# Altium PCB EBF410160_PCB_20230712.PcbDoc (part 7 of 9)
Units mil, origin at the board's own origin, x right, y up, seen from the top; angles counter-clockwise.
Board outline 5393.69 x 3858.26 mil, 6 copper layers (TOP, GND02, ART03, POW04, GND05, BOTTOM), stack 47.2 mil thick; 572 components, 434 nets, 2057 pads, 1177 vias.
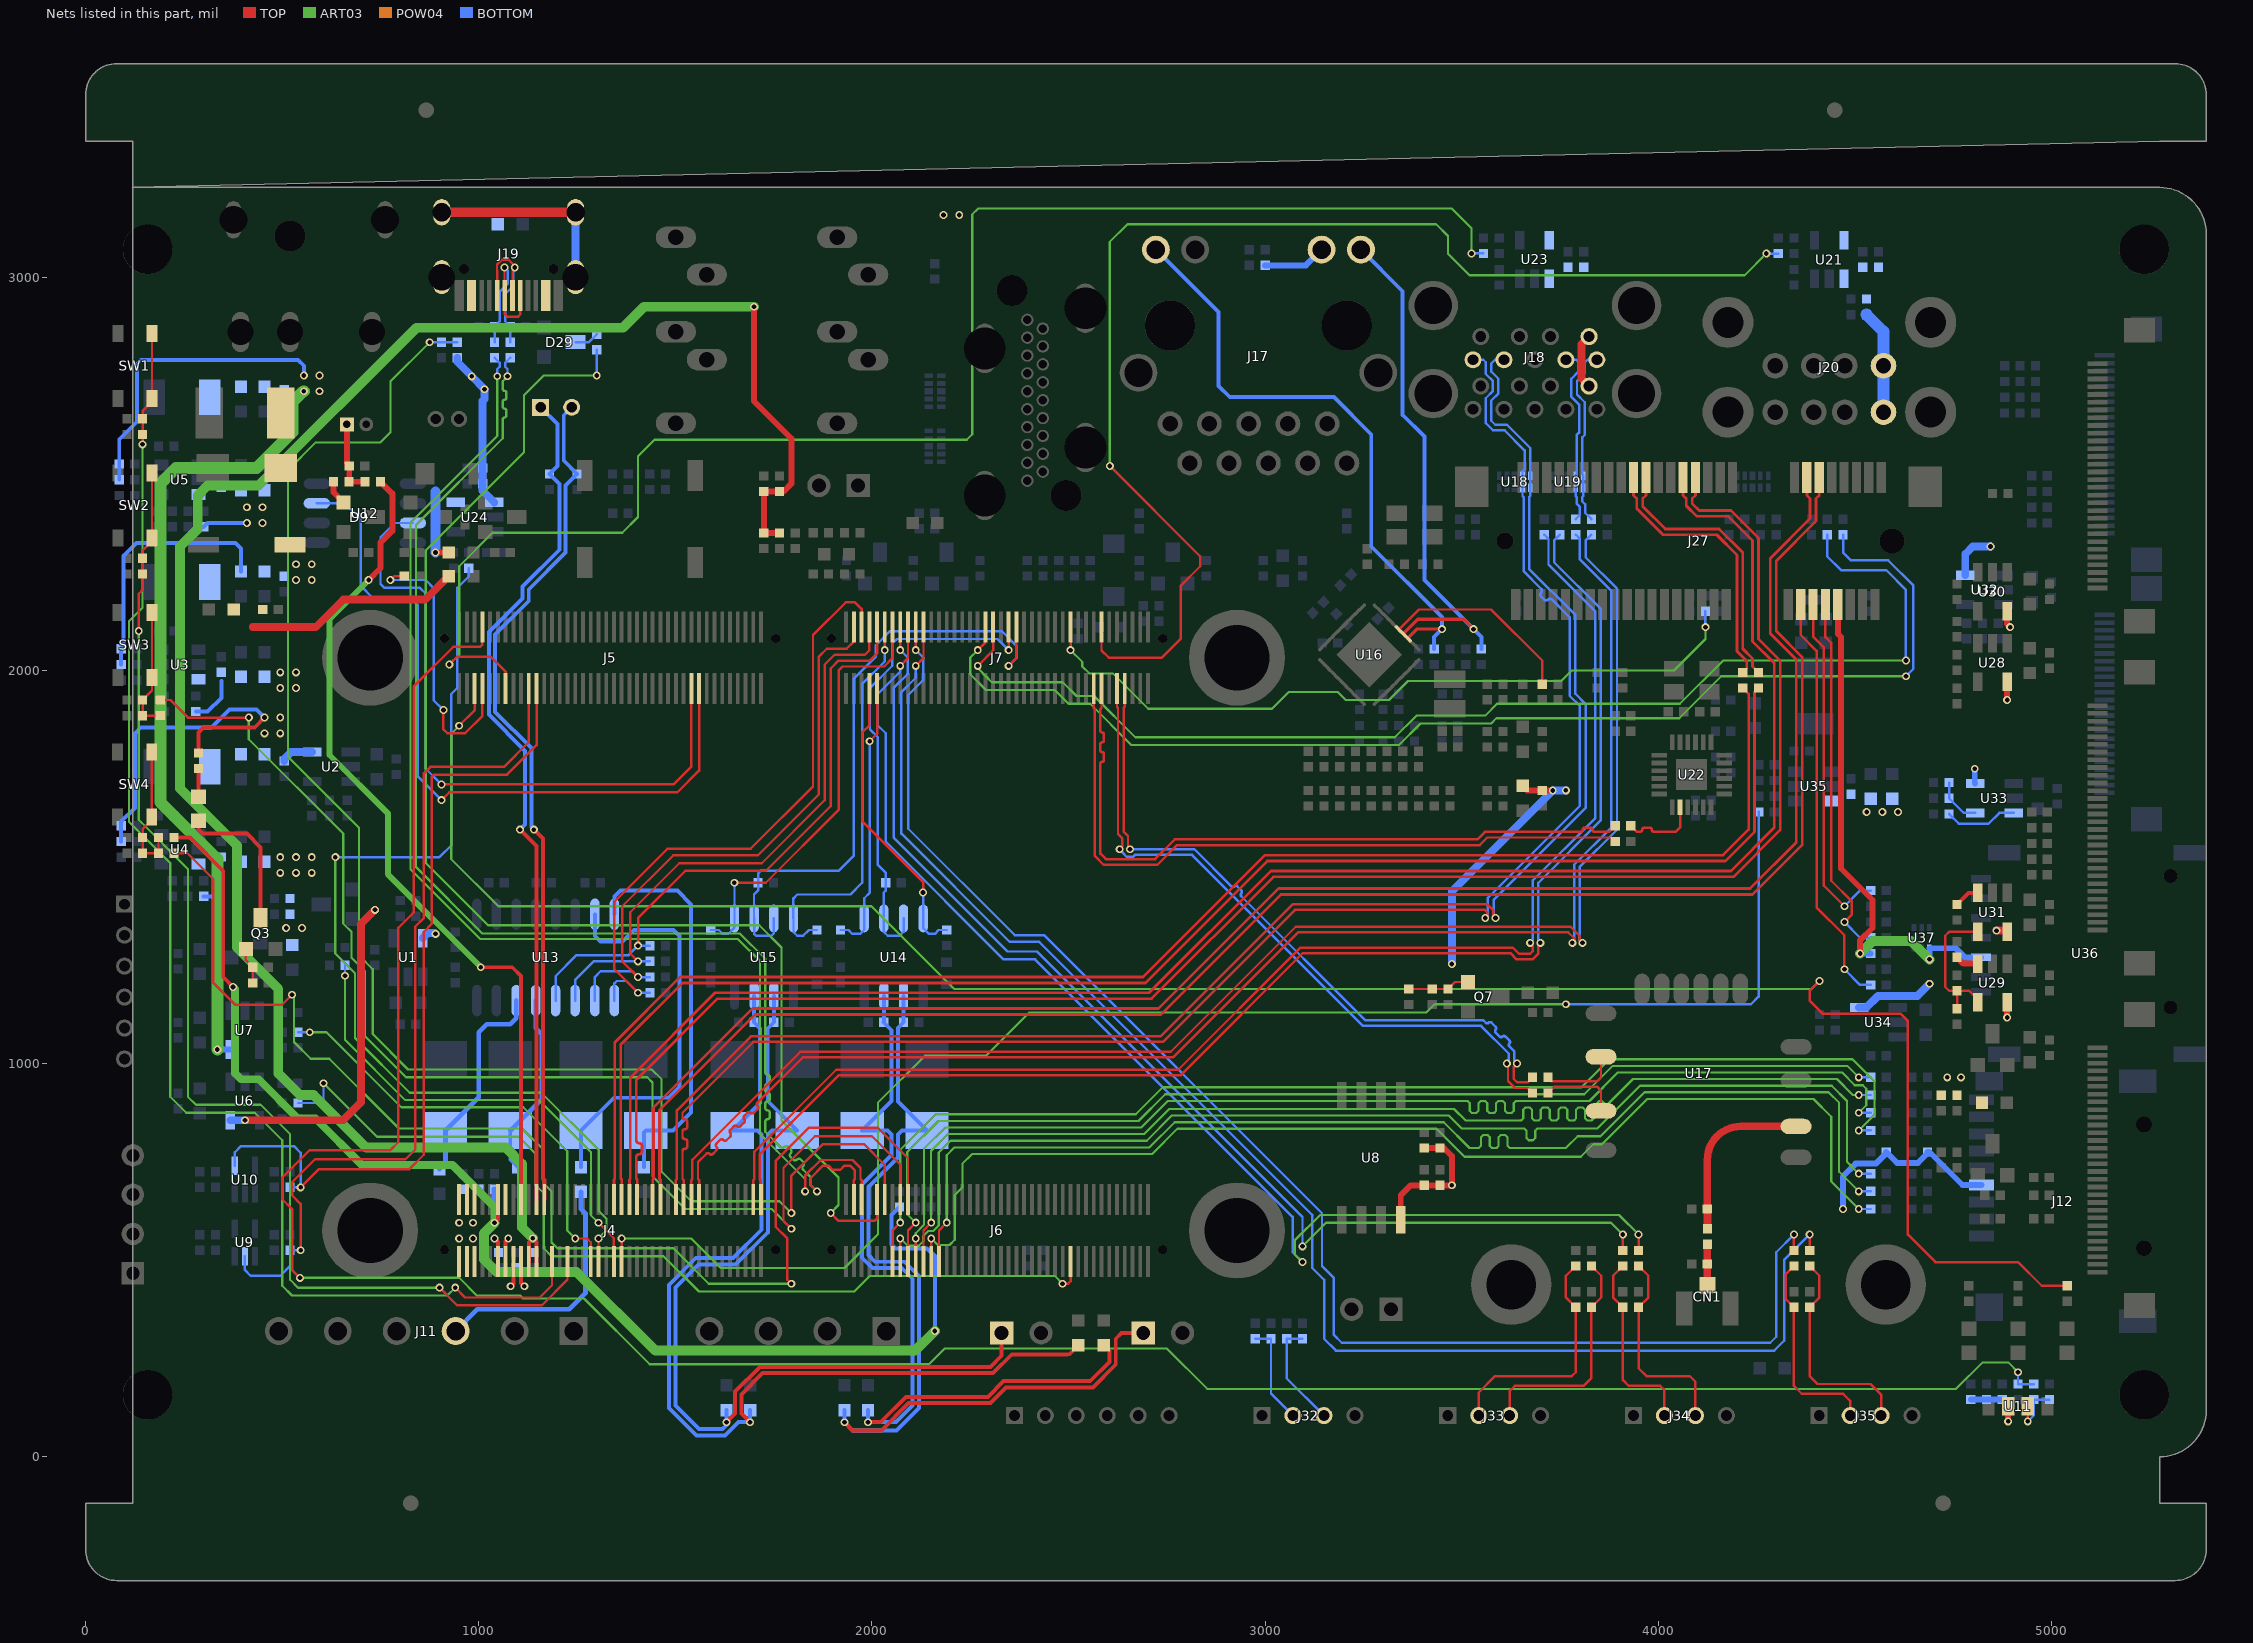
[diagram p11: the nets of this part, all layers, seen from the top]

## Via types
v1: diameter 20, hole 12, TOP to BOTTOM, 1177 vias

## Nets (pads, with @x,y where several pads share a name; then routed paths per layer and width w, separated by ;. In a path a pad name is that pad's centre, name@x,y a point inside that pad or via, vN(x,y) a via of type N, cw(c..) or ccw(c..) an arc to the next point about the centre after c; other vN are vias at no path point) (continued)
N17770942: R142.1 U22.14 | length 201
  TOP w6.23: R142.1@3929.68,1605 3945.45,1589.23 3953.55,1589.23 ccw(c3953.55,1594.62) 3958.94,1594.62 cw(c3964.32,1594.62) 3964.32,1600 3978.47,1600 cw(c3978.47,1594.62) 3983.86,1594.62 ccw(c3989.24,1594.62) 3989.24,1589.23 4044.11,1589.23 4055.47,1600.59 U22.14@4055.47,1652.32
N17861933: C63.1 C64.1 R47.1 U11.2 | length 180.3
  TOP w15: v1(4890,90) U11.2@4890,128.74
  BOTTOM w15: R47.1@4795,145.32 C64.1@4835,145.32 C63.1@4875,145.32 4890,130.32 v1(4890,90)
N17863087: R44.2 R46.2 U11.3 | length 140.3
  TOP w6.16: v1(4940,90) U11.3@4940,128.74
  BOTTOM w6.16: v1(4940,90) 4955,105 R46.2@4955,145.32 R44.2@4995,145.32
N17946485: C60.1 D7.2 R41.1 SW3.3 SW3.4 | length 317.8
  TOP w6.16: SW3.4@168.62,2147.39 SW3.3@168.62,1982.03 168.62,1948.94 D7.2@144.68,1925 C60.1@144.68,1885 189.68,1885 R41.1@190,1885.32
N17975561: D10.2 J10.1 R50.2 R51.1 | length 189.3
  TOP w15: J10.1@664.37,2625.98 664.37,2525.95 D10.2@670.32,2520 670.32,2480.64 R50.2@669.68,2480 R51.1@710.32,2480
N18056005: C107.2 Q7.1 R127.2 R128.2 | length 158.4
  TOP w6.16: R128.2@3365,1189.68 C107.2@3425,1189.68 R127.2@3465,1189.68 3482.82,1207.5 Q7.1@3516,1207.5
N18056634: C104.1 C105.1 U17.2 | length 449.7
  TOP w19: C105.1@4124.78,630 4124.78,755.2 cw(c4209.65,755.2) 4209.65,840.07 U17.2@4350.45,840.08
  TOP w20: C105.1@4124.78,630 4125,629.78 C104.1@4125,579.68
N18056637: C104.2 C106.1 CN1.1 | length 104.7
  TOP w19: CN1.1@4125,435.86 4125,489.68 C106.1@4124.68,490 4124.68,540 C104.2@4125,540.32
N18057325: R126.2 U17.7 | length 195.2
  TOP w6.23: R126.2@3719.68,965 3729.23,955.45 3845.45,955.45 3854.39,964.39 U17.7@3854.39,1017.23
N18057335: R125.2 U17.6 | length 197
  TOP w6.23: R125.2@3719.68,925 3735.9,941.22 3843.78,941.22 3854.39,930.61 U17.6@3854.39,879.44
N18091011: D9.1 R50.1 | length 63.1
  TOP w15: R50.1@630.32,2480 630.32,2453.18 D9.1@656,2427.5
N18111918: C130.1 R170.2 U29.4 U31.4 | length 366
  TOP w6.16: R170.2@4760,1139.68 C130.1@4760,1185.32 ; U29.4@4812.6,1155.79 4812.6,1163.4 4790.68,1185.32 C130.1@4760,1185.32 ; U31.4@4812.6,1335.79 4740.79,1335.79 4730,1325 4730,1195 4739.68,1185.32 C130.1@4760,1185.32
N18111989: R175.1 U31.3 | length 64.8
  TOP w10: R175.1@4760,1404.68 4789.53,1434.21 U31.3@4812.6,1434.21
N18112037: R172.1 U29.3 | length 59.3
  TOP w15: R172.1@4760,1270.32 4776.11,1254.21 U29.3@4812.6,1254.21
N18115454: R187.1 U33.3 | length 186.3
  BOTTOM w6.16: R187.1@4739.68,1635 4764.68,1610 4840,1610 4867.6,1637.6 U33.3@4904.21,1637.6
N18115527: C143.1 R186.2 U33.4 | length 121.6
  BOTTOM w6.16: R186.2@4739.68,1715 C143.1@4739.68,1675 4777.08,1637.6 U33.4@4805.79,1637.6
N18173560: J19.C1 J19.C2 J19.C3 J19.C4 L8.1 | length 505.2
  TOP w25: J19.C2@905.83,3165.28 J19.C1@1246.03,3165.28
  BOTTOM w20: J19.C3@1246.03,3000.28 J19.C1@1246.03,3165.28
N18175084: D29.3 R135.1 | length 62.2
  BOTTOM w6.16: D29.3@1246,2835 1280.32,2835 R135.1@1300,2854.68
N18245213: LED1.1 Q3.3 | length 378.3
  TOP w10: LED1.1@287,1617.69 287,1595 297,1585 410,1585 445,1550 Q3.3@445,1371
N18245628: LED1.2 R16.2 | length 72
  TOP w10: LED1.2@287,1678.32 R16.2@287,1750.32
N18246356: Q3.1 R19.2 R21.1 | length 93.4
  TOP w6.16: Q3.1@407.5,1291 407.5,1262.82 R21.1@425.32,1245 R19.2@425.32,1205
N18288623: C61.1 D8.2 R43.1 R227.1 SW4.3 SW4.4 | length 348.2
  TOP w6.16: SW4.4@168,1792.95 SW4.3@168,1627.59 168,1619.71 144.68,1596.39 D8.2@144.68,1575 C61.1@144.68,1535 R43.1@185.32,1535 R227.1@185.32,1575
N18353176: J17.12 R115.1 | length 160.4
  BOTTOM w15: R115.1@3000,3030.32 3103.64,3030.32 J17.12@3143.76,3070.44
N18355550: J11.3 R57.2 | length 632.3
  BOTTOM w12: J11.3@941.14,319.64 996.5,375 1230,375 1271.52,416.51 1271.52,618.49 1260,630 R57.2@1260,673.5
N18579208: D48.2 J33.2 R219.1 | length 618
  TOP w6.16: J33.2@3543.3,104.49 3543.3,163.3 3585,205 3780,205 3790,215 D48.2@3790,380.32 3765,405.32 3765,460.32 R219.1@3790,485.32
N18579211: D47.2 J33.3 R220.1 | length 590.2
  TOP w6.16: J33.3@3622.04,104.49 3622.04,167.04 3635,180 3810,180 3830,200 D47.2@3830,380.32 3855,405.32 3855,460.32 R220.1@3830,485.32
N18585387: D50.2 J32.2 R222.1 | length 259
  BOTTOM w6.16: R222.1@2975,300.32 D50.2@3015,300.32 3015,160.35 J32.2@3070.86,104.49
N18585389: D49.2 J32.3 R221.1 | length 275
  BOTTOM w6.16: R221.1@3095,300.32 D49.2@3055,300.32 3055,199.09 J32.3@3149.6,104.49
N18585721: D52.2 J34.2 R224.1 | length 492.2
  TOP w6.16: R224.1@3910,485.32 3885,460.32 3885,405.32 D52.2@3910,380.32 3910,195 3925,180 4005,180 4015.74,169.26 J34.2@4015.74,104.49
N18585723: D51.2 J34.3 R223.1 | length 525.8
  TOP w6.16: R223.1@3950,485.32 3975,460.32 3975,405.32 D51.2@3950,380.32 3950,225 3970,205 4080,205 4094.48,190.52 J34.3@4094.48,104.49
N18585912: D54.2 J35.2 R226.1 | length 518.9
  TOP w6.16: R226.1@4345,485.32 4325.92,466.24 4324.12,464.44 4324.12,401.2 D54.2@4345,380.32 4345,180 4365,160 4470,160 4488.18,141.82 J35.2@4488.18,104.49
N18585914: D53.2 J35.3 R225.1 | length 556
  TOP w6.16: R225.1@4385,485.32 4410,460.32 4410,405.32 D53.2@4385,380.32 4385,205 4405,185 4540,185 4566.92,158.08 J35.3@4566.92,104.49
OTG0_DM: D30.2 J19.A7 J19.B7 R133.1 | length 419.4
  TOP w6.23: v1(1065.34,3025) 1065.34,2954.27 J19.A7@1066.13,2953.48 1066.13,2906.23 1072.36,2900 1100,2900 1105.43,2905.43 J19.B7@1105.43,2953.48
  BOTTOM w6.23: R133.1@1040,2834.68 1040,2874.68 D30.2@1039.68,2875 1052.88,2888.2 1052.88,2962.89 1073.82,2983.82 1073.82,3016.53 v1(1065.34,3025)
OTG0_DP: D31.2 J19.A6 J19.B6 R134.1 | length 419.2
  TOP w6.23: J19.B6@1046.43,2953.48 1046.43,3016.88 1046.23,3017.08 1046.23,3032.92 1057.42,3044.11 1076.03,3044.11 1091.34,3028.8 v1(1091.34,3025) 1085.73,3019.39 J19.A6@1085.73,2953.48
  BOTTOM w6.23: R134.1@1080,2834.68 1080.32,2835 D31.2@1080.32,2875 1067.12,2888.2 1067.12,2956.99 1088.05,2977.92 1088.05,3021.7 v1(1091.34,3025)
PCIE20_CLKREQN_M0: J7.37 R207.1 | length 3162.1
  TOP w6.16: v1(2268.9,2051.61) 2288.58,2071.3 J7.37@2288.58,2110.98
  ART03 w5.61: v1(2268.9,2051.61) 2250,2032.71 2250,1990 2290,1950 2465,1950 2500,1915 2555,1915 2660,1810 3340,1810 3395,1865 3575,1865 3588.2,1878.19 4053.2,1878.19 4160,1985 v1(4630,1985)
  BOTTOM w6.16: R207.1@4470,2345.32 4470,2300 4490,2280 4585,2280 4649.08,2215.92 4649.08,2004.08 v1(4630,1985)
PCIE20_PERSTN_M0: J7.59 R209.2 | length 1903.3
  TOP w6.16: v1(2505.12,2051.61) J7.59@2505.12,2110.98
  ART03 w5.61: v1(2505.12,2051.61) 2535,2021.73 2535,2010 2552.49,1992.51 2612.49,1992.51 2702.49,1902.51 3017.51,1902.51 3060,1945 3185,1945 3205,1925 3315,1925 3363.2,1973.19 3753.2,1973.19 3780,2000 4040,2000 4120,2080 v1(4120,2110)
  BOTTOM w6.16: v1(4120,2110) R209.2@4120,2150.32
PCIE20_REFCLKN: J4.54 J27.11 | length 4422.1
  TOP w7.03: J4.54@1461.8,654.29 1461.8,704.82 1459.48,707.15 1459.48,882.22 1702.26,1125 2735.03,1125 3040,1429.97 4239.97,1429.97 4366,1556 4366,2034 4300,2100 4300,2278.74 4401.27,2380.01 4401.27,2436.82 4409.5,2445.05 J27.11@4409.5,2490.88
PCIE20_REFCLKP: J4.52 J27.13 | length 4422.1
  TOP w7.03: J4.52@1442.12,654.29 1442.12,704.82 1444.45,707.15 1444.45,888.45 1696.03,1140.03 2728.8,1140.03 3033.77,1445 4233.74,1445 4350.97,1562.23 4350.97,2027.77 4284.97,2093.77 4284.97,2284.97 4386.24,2386.24 4386.24,2436.82 4378.01,2445.05 J27.13@4378.01,2490.88
PCIE20_RXN: J4.48 J27.23 | length 4535
  TOP w7.03: J4.48@1402.75,654.29 1402.75,704.82 1400.42,707.15 1400.42,762.09 cw(c1407.71,762.09) 1407.71,769.37 ccw(c1407.71,776.66) 1415,776.66 1415,790.21 ccw(c1407.71,790.21) 1407.71,797.49 cw(c1407.71,804.78) 1400.42,804.78 1400.42,958.42 1607,1165 2711.35,1165 3021.32,1474.97 4191.23,1474.97 4310.03,1593.77 4310.03,2024.97 4255.03,2079.97 4255.03,2336.97 4185,2407 4104.26,2407 4086.31,2424.95 4086.31,2436.82 4094.54,2445.05 J27.23@4094.54,2490.88
PCIE20_RXP: J4.46 J27.25 | length 4518.4
  TOP w7.03: J4.46@1383.06,654.29 1383.06,704.82 1385.39,707.15 1385.39,964.65 1600.77,1180.03 2705.12,1180.03 3015.09,1490 4185,1490 4295,1600 4295,2018.74 4240,2073.74 4240,2330.74 4178.77,2391.97 4098.03,2391.97 4071.28,2418.72 4071.28,2436.82 4063.05,2445.05 J27.25@4063.05,2490.88
PCIE20_TXN: C165.1 J4.44 | length 3873.4
  TOP w7.03: J4.44@1363.38,654.29 1363.38,704.82 1361.05,707.15 1361.05,1048.05 1517.97,1204.97 2695.64,1204.97 3005.64,1514.97 4171.23,1514.97 4245,1588.74 4245,1945.32 C165.1@4255,1955.32
PCIE20_TXP: C166.1 J4.42 | length 3875.4
  TOP w7.03: J4.42@1343.69,654.29 1343.69,704.82 1346.02,707.15 1346.02,1054.28 1511.74,1220 2689.41,1220 2999.41,1530 4165,1530 4229.97,1594.97 4229.97,1940.35 C166.1@4215,1955.32
PCIE20_WAKEN_M0: J7.39 R206.1 | length 3106.5
  TOP w6.16: v1(2268.9,2011.61) 2308.27,2050.98 J7.39@2308.27,2110.98
  ART03 w5.61: 2292.77,1982.23 2305,1970 2485,1970 2520,1935 2565,1935 2670,1830 3330,1830 3385,1885 3560,1885 3590,1915 4055,1915 4165,2025 v1(4630,2025)
  ART03 w6.16: v1(2268.9,2011.61) 2268.9,2006.1 2292.77,1982.23
  BOTTOM w6.16: R206.1@4430,2345.32 4430,2290 4465,2255 4580,2255 4630,2205 v1(4630,2025)
PCIE_PWR_EN: J4.43 R204.1 | length 3933.1
  TOP w6.16: J4.43@1363.38,496.81 v1(1363.38,555)
  ART03 w5.61: v1(1363.38,555) 1540,555 1615,480 1930,480 2015,565 2015,900 2135,1020 2290,1020 2400,1130 3410,1130 3430.97,1150.97 v1(3765,1150.97)
  BOTTOM w6.16: v1(3765,1150.97) 4235.97,1150.97 4255.32,1170.32 R204.1@4255.32,1640
PE_TXN: C165.2 J27.31 | length 701.9
  TOP w7.03: J27.31@3968.56,2490.88 3968.56,2445.05 3960.32,2436.82 3960.32,2417.68 4018,2360 4155,2360 4215,2300 4215,2055 4240,2030 4240,2009.68 C165.2@4255,1994.68
PE_TXP: C166.2 J27.33 | length 699.8
  TOP w7.03: J27.33@3937.06,2490.88 3937.06,2445.05 3945.3,2436.82 3945.3,2411.45 4011.77,2344.97 4148.77,2344.97 4199.97,2293.77 4199.97,2048.78 4224.97,2023.78 4224.97,2004.65 C166.2@4215,1994.68
PHY1_LED1: J17.14 R116.1 U16.33 | length 1578
  TOP w8: U16.33@3362.44,2081.76 3385.68,2105 v1(3450,2105)
  BOTTOM w10: J17.14@2722.1,3070.44 2881.27,2911.27 2881.27,2723.73 2910,2695 3175,2695 3270,2600 3270,2315.62 3450,2135.62 v1(3450,2105) 3430,2085 R116.1@3430,2054.68
PHY1_LED2: J17.11 R117.1 U16.34 | length 1347
  TOP w8: U16.34@3351.3,2092.9 3388.4,2130 3505,2130 v1(3530,2105)
  BOTTOM w10: J17.11@3243.76,3070.44 3350,2964.2 3350,2650 3405,2595 3405,2230 v1(3530,2105) 3550,2085 R117.1@3550,2054.68
PHY_CLKOUT125: R112.2 U16.35 | length 500.1
  TOP w6.16: U16.35@3340.16,2104.03 3391.13,2155 3575,2155 3705,2025 R112.2@3705,1964.68
PWM2_M0: J5.8 R17.1 | length 718.9
  TOP w6.16: v1(775,2230) 785,2240 R17.1@810.32,2240 ; v1(909.99,1899.13) 909.99,1850.01 919.95,1840.05 965.05,1840.05 1009.05,1884.05 J5.8@1009.05,1953.5
  BOTTOM w6.16: v1(775,2230) 865,2230 885,2210 885,1924.12 v1(909.99,1899.13)
PWM3_IR: C62.1 J5.7 R46.1 | length 6674.1
  TOP w6.16: v1(545,455) 525,475 525,630 500,655 500,710 570,780 775,780 795,800 795,1345 835,1385 835,1960 935,2060 1002.89,2060 1009.05,2066.16 J5.7@1009.05,2110.98
  ART03 w5.61: v1(545,455) 950,455 995,410 1105,410 1112.5,402.5 1267.5,402.5 1435,235 2144.82,235 2184.82,275 2750,275 2852.5,172.5 4757.5,172.5 4825,240 4890,240 v1(4915,215)
  BOTTOM w6.16: v1(4915,215) C62.1@4915,184.68 R46.1@4955,184.68
PWR_3V3_EN: J6.59 R30.1 | length 2435.9
  TOP w6.16: v1(2484.8,440) 2498.96,440 2505.12,446.16 J6.59@2505.12,496.81
  ART03 w5.61: v1(605,950) 741,814 1101,814 1145,770 1145,690 1165,670 1165,530 1185,510 1470,510 1560,420 1955,420 1995,460 2464.8,460 v1(2484.8,440)
  BOTTOM w6.16: R30.1@540,899.68 594.68,899.68 605,910 v1(605,950)
PWR_5V_EN: J4.35 R32.1 | length 1132.7
  TOP w6.16: v1(1245.27,555) 1275,555 1284.64,545.36 J4.35@1284.64,496.81
  ART03 w5.61: v1(570,1079.68) 612.32,1079.68 803,889 1113,889 1225,777 1225,575.27 v1(1245.27,555)
  BOTTOM w6.16: R32.1@540,1079.68 v1(570,1079.68)
PWR_12V_EN: J4.41 R28.1 | length 1235.7
  TOP w6.16: v1(1304.32,595) 1343.69,555.63 J4.41@1343.69,496.81
  ART03 w5.61: v1(659.68,1223.2) 659.68,1060.32 813,907 1153,907 1285,775 1285,614.32 v1(1304.32,595)
  BOTTOM w6.16: v1(659.68,1223.2) R28.1@659.68,1250
PWRON_KEY: C56.1 D3.2 J4.25 SW1.3 SW1.4 | length 3499.1
  TOP w6.16: v1(144.68,2575) C56.1@144.68,2600 D3.2@144.68,2640 144.68,2660.2 168.62,2684.14 SW1.3@168.62,2691.99 SW1.4@168.62,2857.35 ; v1(940,430) 965,405 1155,405 1186.21,436.21 J4.25@1186.21,496.81
  ART03 w5.61: v1(144.68,2575) 144.68,2159.68 110,2125 110,1615 215,1510 215,915.61 255.61,875 430,875 500,805 500,435 525,410 920,410 v1(940,430)
RECOVERY: J6.16 R41.2 | length 3215.5
  TOP w6.16: R41.2@190,1924.68 215.32,1924.68 260,1880 v1(415,1880) ; v1(1795,580) 1775,600 1775,735 1855,815 2000,815 2072.05,742.95 J6.16@2072.05,654.29
  ART03 w5.61: v1(415,1880) 415,1825 655,1585 655,1356 676.49,1334.52 676.49,1268.52 710,1235 710,1070 815,965 1428.7,965 1441.74,951.96 1441.74,713.26 1525,630 1745,630 v1(1795,580)
RESET_KEY: C58.1 D4.2 J4.29 SW2.3 SW2.4 | length 3128
  TOP w6.16: v1(135,2100) 135,2195 144.68,2204.68 C58.1@144.68,2245 D4.2@144.68,2285 144.68,2305.2 168.62,2329.14 SW2.3@168.62,2337.05 SW2.4@168.62,2502.41 ; v1(900,430) 945,385 1160,385 1225.58,450.58 J4.29@1225.58,496.81
  ART03 w5.61: v1(135,2100) 135,1620 260,1495 260,915.61 280.61,895 445,895 520,820 520,450 540,430 v1(900,430)
RS485_1_A: D26.2 J13.1 R71.2 R80.1 U14.6 | length 2443.4
  TOP w10: v1(1930,87.75) 1951,66.75 2023.92,66.75 2093.35,136.18 2301.41,136.18 2341.45,176.22 2561.83,176.22 2620,234.39 2620,300 2635,315 J13.1@2690,315
  BOTTOM w10: R80.1@1930,118.5 v1(1930,87.75) 1951,66.75 2062.26,66.75 2119.12,123.61 2119.12,459.21 2082.4,495.93 2007.74,495.93 1991,512.67 1991,686 2066,761 2066,819.45 2076,829.45 D26.2@2140,829.45 2066,903.45 2066,1090.68 R71.2@2080.32,1105 U14.6@2080.32,1172.32
RS485_1_B: D24.2 R73.1 R76.1 R79.1 U14.7 | length 2166.1
  TOP w10: v1(1990,87.75) 2022.29,87.75 2086.72,152.18 2294.78,152.18 2334.82,192.22 2555.2,192.22 2604,241.02 2604,269.5 R73.1@2590,283.5
  BOTTOM w10: R79.1@1990,118.5 v1(1990,87.75) 2060.63,87.75 2103.12,130.24 2103.12,452.58 2075.77,479.93 2001.11,479.93 1975,506.04 1975,692.63 2050,767.63 2050,819.45 2040,829.45 D24.2@1975,829.45 2050,904.45 2050,1084.68 R76.1@2029.68,1105 2030.32,1105.64 U14.7@2030.32,1172.32
RS485_2_A: D27.2 J14.1 R72.2 R82.1 U15.6 | length 2360.2
  TOP w10: v1(1630,87.75) 1651.89,109.64 1651.89,165.35 1715.04,228.5 2301.63,228.5 2330,256.87 J14.1@2330,315
  BOTTOM w10: R82.1@1630,118.5 v1(1630,87.75) 1630,80 1620,70 1560,70 1500,130 1500,430.66 1558.34,489 1653.34,489 1735,570.66 1735,819.45 1745,829.45 D27.2@1810,829.45 1735,904.45 1735,1089.68 R72.2@1750.32,1105 U15.6@1750.32,1172.32
RS485_2_B: D25.2 R74.1 R78.1 R81.1 U15.7 | length 2574.1
  TOP w10: v1(1690,87.75) 1667.89,109.86 1667.89,158.72 1721.67,212.5 2308.26,212.5 2355.61,259.85 2496.35,259.85 2497.18,260.68 2502.18,260.68 R74.1@2525,283.5
  BOTTOM w10: R81.1@1690,118.5 v1(1690,87.75) 1660.38,87.75 1626.63,54 1553.37,54 1484,123.37 1484,437.29 1551.71,505 1646.71,505 1719,577.28 1719,819.45 1709,829.45 D25.2@1645,829.45 1715,899.45 1715,1089.68 R78.1@1699.68,1105 1699.68,1171.68 U15.7@1700.32,1172.32
RX8010_NIRQ1: J5.64 U12.7 | length 1878.8
  TOP w6.16: v1(905,1670) 925,1690 1505,1690 1560.23,1745.23 J5.64@1560.23,1953.5
  BOTTOM w6.16: U12.7@587.95,2425 660,2425 700,2385 700,2215 730,2185 825,2185 845,2165 845,1730 v1(905,1670)
RX8010_NIRQ2: J5.62 U12.3 | length 1695.2
  TOP w6.16: v1(905,1710) 1495,1710 1540.54,1755.54 J5.62@1540.54,1953.5
  BOTTOM w6.16: U12.3@832.05,2375 786.16,2375 750,2338.84 750,2220 760,2210 850,2210 865,2195 865,1750 v1(905,1710)
RXD1_232: D12.2 R58.1 U13.13 | length 471.4
  BOTTOM w10: D12.2@1080,829.45 1080,756.5 R58.1@1100,736.5
  BOTTOM w12: D12.2@1080,829.45 1160,909.45 1160,1075 1144.8,1090.2 U13.13@1144.8,1160.2
RXD2_232: D11.2 R56.1 U13.8 | length 1019.9
  BOTTOM w10: U13.8@1344.8,1379.8 1344.8,1424.8 1360,1440 1505,1440 1540,1405 1540,875 1494.45,829.45 D11.2@1425,829.45 1420,824.45 R56.1@1420,736.5
SARADC_VIN1: J6.18 R43.2 | length 3230.1
  TOP w6.16: R43.2@224.68,1535 258.84,1535 325,1468.84 325,1205 380,1150 500,1150 v1(525,1175) ; v1(1795,440) 1785,450 1785,555 1755,585 1755,752 1840,837 2014,837 2091.73,759.27 J6.18@2091.73,654.29
  ART03 w5.61: v1(525,1175) 530,1170 530,1055 572.5,1012.5 619.5,1012.5 797,835 1110,835 1165,780 1165,695 1185,675 1185,545 1200,530 1495,530 1585,440 v1(1795,440)
SDMMC0_CLK: J6.13 R63.1 | length 3060.5
  TOP w6.16: J6.13@2052.36,496.81 2052.36,575.62 v1(2072.05,595.31)
  ART03 w5.61: v1(2072.05,595.31) 2072.05,780.85 2162.18,870.98 2670.98,870.98 2740,940 3805,940 3875.98,1010.98 4494.02,1010.98 4550,955 4550,870 v1(4510,830)
  BOTTOM w6.16: v1(4510,830) R63.1@4540.32,830
SDMMC0_CMD: J6.15 R62.1 | length 3077.5
  TOP w6.16: J6.15@2072.05,496.81 v1(2072.05,555.31)
  ART03 w5.61: v1(2072.05,555.31) 2090.85,536.5 2119.21,536.5 2130.22,547.52 2130.22,561.34 2142.99,574.12 2156.19,574.12 2170,587.93 2170,773.66 2200,803.66 2698.87,803.66 2762.89,867.68 3467.32,867.68 3500,835 3659.03,835 3664.64,829.39 3664.64,810.61 3670.25,805 3681.47,805 3687.08,810.61 3687.08,829.39 3692.69,835 3845,835 3953.66,943.66 4441.34,943.66 4480,905 4480,750 v1(4510,720)
  BOTTOM w6.16: v1(4510,720) R62.1@4540.32,720
SDMMC0_D0: J6.19 R64.1 | length 3034.2
  TOP w6.16: J6.19@2111.42,496.81 v1(2111.42,555.31)
  ART03 w5.61: v1(2111.42,555.31) 2111.42,568.71 2131.98,589.28 2131.98,783.25 2186.06,837.32 2684.92,837.32 2752.6,905 3514.66,905 3520.28,899.39 3520.28,879.75 3525.89,874.14 3537.11,874.14 3542.72,879.75 3542.72,899.39 3548.32,905 3559.55,905 3565.16,899.39 3565.16,879.75 3570.76,874.14 3581.99,874.14 3587.59,879.75 3587.59,899.39 3593.2,905 3604.43,905 3610.03,899.39 3610.03,879.75 3615.64,874.14 3626.86,874.14 3632.47,879.75 3632.47,899.39 3638.09,905 3825,905 3897.32,977.32 4467.68,977.32 4500,945 4520,945 4528.81,936.2 4528.81,893.8 v1(4510,875)
  BOTTOM w6.16: v1(4510,875) R64.1@4540.32,875
SDMMC0_D1: J6.21 R65.1 | length 3039.1
  TOP w6.16: J6.21@2131.1,496.81 2131.1,575.62 v1(2150.79,595.31)
  ART03 w5.61: v1(2150.79,595.31) 2150,596.1 2150,777.46 2193.03,820.49 2691.9,820.49 2755.92,884.51 3480.49,884.51 3510,855 3650.84,855 3656.45,860.61 3656.45,882.56 3662.06,888.17 3673.28,888.17 3678.89,882.56 3678.89,860.61 3684.5,855 3695.72,855 3701.33,860.61 3701.33,882.56 3706.94,888.17 3718.16,888.17 3723.77,882.56 3723.77,860.61 3729.38,855 3740.6,855 3746.21,860.61 3746.21,882.56 3751.82,888.17 3763.04,888.17 3768.65,882.56 3768.65,860.61 3774.26,855 3785.48,855 3791.09,860.61 3791.09,882.56 3796.7,888.17 3807.92,888.17 3813.53,882.56 3813.53,860.61 3819.14,855 3830.36,855 3848.51,873.15 3848.51,881.08 3841.26,888.33 3841.26,896.26 3849.2,904.2 3857.13,904.2 3864.38,896.95 3872.31,896.95 3935.85,960.49 4454.51,960.49 4495,920 v1(4510,920)
  BOTTOM w6.16: v1(4510,920) R65.1@4540.32,920
SDMMC0_D2: J6.23 R60.1 | length 2982
  TOP w6.16: J6.23@2150.79,496.81 v1(2150.79,555.31)
  ART03 w5.61: v1(2150.79,555.31) 2167.59,538.5 2197.12,538.5 2210.72,552.11 2210.72,665.72 2230,685 2230,745 2255,770 2712.81,770 2776.83,834.02 3435.98,834.02 3506.97,763.03 3803.03,763.03 3835,795 3857,795 3972,910 4395,910 4440,865 4440,700 v1(4510,630)
  BOTTOM w6.16: v1(4510,630) R60.1@4540.32,630
SDMMC0_D3: J6.25 R61.1 | length 3062.6
  TOP w6.16: J6.25@2170.47,496.81 2170.47,575.62 v1(2190.16,595.31)
  ART03 w5.61: v1(2190.16,595.31) 2190,595.47 2190,766.83 2210,786.83 2705.84,786.83 2769.86,850.85 3454.15,850.85 3520,785 3543.45,785 3549.06,790.61 3549.06,812.56 3554.67,818.17 3565.89,818.17 3571.5,812.56 3571.5,790.61 3577.11,785 3588.33,785 3593.94,790.61 3593.94,812.56 3599.55,818.17 3610.77,818.17 3616.38,812.56 3616.38,790.61 3621.99,785 3765,785 3795,815 3853.2,815 3965.03,926.83 4433.17,926.83 4460,900 4460,725 v1(4510,675)
  BOTTOM w6.16: v1(4510,675) R61.1@4540.32,675
SDMMC0_DET: J6.17 R66.1 | length 2848.4
  TOP w6.16: J6.17@2091.73,496.81 2091.73,575.62 v1(2111.42,595.31)
  ART03 w5.61: v1(2111.42,595.31) 2090,616.73 2090,775 2169.15,854.15 2677.95,854.15 2745.63,921.83 3811.83,921.83 3884.15,994.15 4480.85,994.15 v1(4510,965)
  BOTTOM w6.16: v1(4510,965) R66.1@4540.32,965
SIM_CLK0: J27.12 R200.1 | length 884.5
  TOP w6.16: J27.12@4393.76,2168.04 4393.76,2086.24 4421.34,2058.66 4421.34,1452.18 v1(4473.52,1400)
  BOTTOM w6.16: v1(4473.52,1400) 4513.52,1440 R200.1@4540.32,1440
SIM_DATA0: J27.10 R202.1 | length 927.2
  TOP w6.16: J27.10@4425.25,2168.04 4425.25,2084.75 4440,2070 4440,1465 4492.6,1412.4 4492.6,1379.08 v1(4473.52,1360)
  BOTTOM w6.16: v1(4473.52,1360) 4513.52,1320 R202.1@4540.32,1320
SIM_RST0: J27.14 R199.1 | length 1057.5
  TOP w6.16: J27.14@4362.26,2168.04 4362.26,2090.25 4402.68,2049.83 4402.68,1397.32 4473.52,1326.48 v1(4473.52,1240)
  BOTTOM w6.16: v1(4473.52,1240) 4513.52,1200 R199.1@4540.32,1200
SIM_VDD: J27.8 R198.1 U36.1 U37.1 | length 1342.9
  TOP w15: J27.8@4456.75,2168.04 4456.75,2093.25 4465,2085 4465,1496 4545,1416 4545,1345 4513.52,1313.52 v1(4513.52,1280)
  ART03 w25: v1(4513.52,1280) 4545.52,1312 4642.69,1312 v1(4689.69,1265)
  BOTTOM w15: v1(4513.52,1280) R198.1@4540.32,1280 ; v1(4689.69,1265) U37.1@4689.69,1293.42 4756.57,1293.42 4779.84,1270.16 U36.1@4821.24,1270.16
SPKN_OUT: D46.2 J4.24 J31.2 | length 2175.7
  TOP w10: v1(1140,1595) 1162.84,1572.16 1162.84,707.16 1166.53,703.47 J4.24@1166.53,654.29
  BOTTOM w10: v1(1140,1595) 1134,1601 1134,1802.13 1041.39,1894.74 1041.39,2091.14 1127,2176.74 1127,2206.32 1221,2300.32 1221,2470.68 D46.2@1250,2499.68 1216,2533.68 1216,2649.07 J31.2@1236.22,2669.29
SPKP_OUT: D45.2 J4.22 J31.1 | length 2186.7
  TOP w10: v1(1105,1595) 1146.84,1553.16 J4.22@1146.84,654.29
  BOTTOM w10: v1(1105,1595) 1118,1608 1118,1795.51 1025.39,1888.11 1025.39,2097.76 1111,2183.37 1111,2212.95 1205,2306.95 1205,2474.68 D45.2@1180,2499.68 1200,2519.68 1200,2626.77 J31.1@1157.48,2669.29
SS_TXN: C112.1 J18.8 U19.2 U19.9 | length 461.9
  BOTTOM w6.23: J18.8@3765.02,2790.12 3791.05,2790.12 3797.28,2783.89 3797.28,2760.03 3779.08,2741.83 3779.08,2695.92 3798.76,2676.24 3798.76,2605.05 3792.41,2598.7 3792.41,2498.47 U19.9@3789.69,2495.75 U19.2@3789.69,2464.25 3789.69,2443.63 3792.41,2440.91 3792.41,2424.11 3800,2416.52 3800,2394.68 C112.1@3790,2384.68
SS_TXP: C113.1 J18.9 U19.1 U19.10 | length 462.9
  BOTTOM w6.23: C113.1@3830,2384.68 3814.23,2400.45 3814.23,2422.41 3806.64,2430 3806.64,2440.91 3809.37,2443.63 U19.1@3809.37,2464.25 U19.10@3809.37,2495.75 3806.64,2498.47 3806.64,2592.81 3812.99,2599.15 3812.99,2682.14 3793.31,2701.82 3793.31,2735.94 3811.51,2754.13 3811.51,2781.51 3820.12,2790.12 J18.9@3843.76,2790.12
TXD1_232: D14.2 R59.1 U13.14 | length 544.7
  BOTTOM w12: R59.1@900,731.5 915,746.5 D14.2@915,829.45 1000,914.45 1000,1080 1020,1100 1080,1100 1095.2,1115.2 U13.14@1095.2,1160.2
TXD2_232: D13.2 R57.1 U13.7 | length 1068.3
  BOTTOM w10: R57.1@1260,736.5 D13.2@1260,829.45 1343.55,913 1483,913 1510,940 1510,1325 1495,1340 1395,1340 1365,1310 1310,1310 1295.2,1324.8 U13.7@1295.2,1379.8
UART1_DIR: J7.43 R75.1 U14.2 U14.3 | length 1239.9
  TOP w6.16: v1(2347.64,2051.61) J7.43@2347.64,2110.98
  BOTTOM w6.16: U14.3@2080.32,1369.17 2080.32,1335.32 2070,1325 2040,1325 2030.32,1334.68 U14.2@2030.32,1369.17 2030,1369.49 2030,1434.8 2035.32,1440.12 R75.1@2035.32,1460 2035.32,1484.68 2015,1505 2015,1830 1995,1850 1995,1955 2051.76,2011.76 2051.76,2067.89 2063.86,2080 2319.25,2080 v1(2347.64,2051.61)
UART1_RX_M0: J7.10 R69.2 U14.1 | length 695.3
  TOP w6.16: v1(1994.08,1820) 2012.99,1838.91 J7.10@2012.99,1953.5
  BOTTOM w6.16: R69.2@1920,1339.68 1940.32,1339.68 1950,1330 1970,1330 1980.32,1340.32 U14.1@1980.32,1369.17 1980.32,1420.32 1994.08,1434.08 v1(1994.08,1820)
UART1_TX_M0: J7.8 R67.2 U14.4 | length 750.5
  TOP w6.16: J7.8@1993.31,1953.5 1993.31,1860 1975,1841.69 1975,1616.98 2130,1461.98 v1(2130,1435)
  BOTTOM w6.16: v1(2130,1435) 2130.32,1434.68 U14.4@2130.32,1369.17 2130.32,1344.68 2145,1330 2160,1330 2169.68,1339.68 R67.2@2190,1339.68
UART2_RX_M0_DEBUG: J5.22 R42.2 U10.4 | length 2090.4
  TOP w6.16: v1(546.8,685.03) 593.38,731.62 823.38,731.62 860,768.24 860,1335 880,1355 880,1728.84 886.16,1735 1071.84,1735 1146.84,1810 J5.22@1146.84,1953.5
  BOTTOM w6.16: U10.4@379.41,740.43 379.41,774.41 395,790 530,790 546.8,773.2 v1(546.8,685.03) 545,685.03 544.72,685.32 R42.2@520,685.32
UART2_TX_M0_DEBUG: J5.20 R38.2 U9.2 | length 2164.1
  TOP w6.16: v1(546.8,525.32) 546.8,643.2 525,665 525,698.24 583.38,756.62 813.38,756.62 838.32,781.56 838.32,1348.32 860.32,1370.32 860.32,1738.15 876.85,1754.68 1063.69,1754.68 1127.16,1818.15 J5.20@1127.16,1953.5
  BOTTOM w6.16: U9.2@405,509.57 405,475 420,460 495,460 520,485 R38.2@520,525.32 v1(546.8,525.32)
UART3_RX_M1: J7.5 R52.2 U13.9 | length 1627.5
  TOP w6.16: v1(1405,1180) 1345,1240 1345,1411.57 1479.75,1546.32 1691.32,1546.32 1850,1705 1850,2090 1933.14,2173.14 1956.86,2173.14 1973.62,2156.38 J7.5@1973.62,2110.98
  BOTTOM w6.16: U13.9@1344.8,1160.2 1344.8,1203.84 1350.96,1210 1375,1210 v1(1405,1180) R52.2@1435.32,1180
UART3_TX_M1: J7.3 R53.2 U13.10 | length 1519.4
  TOP w6.16: v1(1405,1220) 1365,1260 1365,1400 1494.37,1529.37 1709.37,1529.37 1865,1685 1865,2035 1885,2055 1935.41,2055 1953.94,2073.53 J7.3@1953.94,2110.98
  BOTTOM w6.16: U13.10@1295.2,1160.2 1295.2,1220.2 1310,1235 1390,1235 v1(1405,1220) R53.2@1435.32,1220
UART4_RX_M1: J7.9 R54.2 U13.12 | length 1564.1
  TOP w6.16: v1(1405,1300) 1405,1370 1525,1490 1730,1490 1895,1655 1895,2005 1915,2025 1995,2025 2012.99,2042.99 J7.9@2012.99,2110.98
  BOTTOM w6.16: U13.12@1195.2,1160.2 1195.2,1222.23 1248.89,1275.92 1380.92,1275.92 v1(1405,1300) R54.2@1435.32,1300
UART4_TX_M1: J7.7 R55.2 U13.11 | length 1542.1
  TOP w6.16: v1(1405,1260) 1385,1280 1385,1385 1509.68,1509.68 1719.68,1509.68 1880,1670 1880,2015 1905,2040 1982.16,2040 1993.31,2051.15 J7.7@1993.31,2110.98
  BOTTOM w6.16: U13.11@1244.8,1160.2 1244.8,1212.8 1292,1260 v1(1405,1260) R55.2@1435.32,1260
UART6_DIR: J7.45 R77.1 U15.2 U15.3 | length 1625.5
  TOP w6.16: v1(2347.64,2011.61) 2367.32,2031.3 J7.45@2367.32,2110.98
  BOTTOM w6.16: U15.3@1750.32,1369.17 1750.32,1331.16 1744.16,1325 1705,1325 1700.32,1329.68 U15.2@1700.32,1369.17 1700,1369.49 1700,1429.8 1710.32,1440.12 R77.1@1710.32,1460 1710.32,1483.84 1716.48,1490 1915,1490 1953.33,1528.33 1953.33,1978.33 2010,2035 2010,2063.84 2046.16,2100 2330,2100 2366.72,2063.28 2366.72,2030.69 v1(2347.64,2011.61)
UART6_RX_M0: J7.13 R70.2 U15.1 | length 1111.8
  TOP w6.16: v1(1650,1460) 1730,1460 1915,1645 1915,2000 1925,2010 2031.07,2010 2052.36,2031.3 J7.13@2052.36,2110.98
  BOTTOM w6.16: R70.2@1590,1339.68 1610.32,1339.68 1620,1330 1634.48,1330 1650.32,1345.84 U15.1@1650.32,1369.17 1650.32,1459.68 v1(1650,1460)
UART6_TX_M0: J7.11 R68.2 U15.4 | length 1021.7
  TOP w6.16: v1(2032.68,2051.61) J7.11@2032.68,2110.98
  BOTTOM w6.16: R68.2@1860,1339.68 1839.68,1339.68 1825,1325 1810,1325 1800.32,1334.68 U15.4@1800.32,1369.17 1800,1369.49 1800,1420 1810,1430 1945,1430 1975,1460 1975,1965 2032.68,2022.68 v1(2032.68,2051.61)
UART7_RX_M0: J7.17 R223.2 | length 3168.4
  TOP w6.16: v1(2072.05,2011.61) 2091.73,2031.3 J7.17@2091.73,2110.98 ; R223.2@3950,524.68 v1(3950,565)
  ART03 w5.61: v1(3095,495) 3076.2,513.8 3076.2,551.2 3140,615 3900,615 v1(3950,565)
  BOTTOM w6.16: v1(2072.05,2011.61) 2072.05,1997.05 2013.6,1938.6 2013.6,1861.4 2035,1840 2035,1565 2335,1265 2415,1265 3070,610 3070,520 v1(3095,495)
UART7_TX_M0: J7.15 R224.2 | length 2966.2
  TOP w6.16: v1(2072.05,2051.61) J7.15@2072.05,2110.98 ; R224.2@3910,524.68 v1(3910,565)
  ART03 w5.61: v1(3095,535) 3155,595 3880,595 v1(3910,565)
  BOTTOM w6.16: v1(2072.05,2051.61) 2091.13,2032.53 2091.13,1991.13 2055,1955 2055,1575 2345,1285 2420,1285 3095,610 v1(3095,535)
UART9_RX_M1: J7.21 R225.2 | length 3853.5
  TOP w6.16: v1(2111.42,2011.61) 2131.1,2031.3 J7.21@2131.1,2110.98 ; R225.2@4385,524.68 v1(4385,565)
  BOTTOM w6.16: v1(2111.42,2011.61) 2111.42,1981.42 2075,1945 2075,1585 2350,1310 2425,1310 3120,615 3120,480 3150,450 3150,300 3180,270 4295,270 4320,295 4320,500 v1(4385,565)
UART9_TX_M1: J7.19 R226.2 | length 3775.1
  TOP w6.16: v1(2111.42,2051.61) J7.19@2111.42,2110.98 ; R226.2@4345,524.68 v1(4345,565)
  BOTTOM w6.16: v1(2111.42,2051.61) 2130.5,2032.53 2130.5,1975.5 2092.34,1937.34 2092.34,1597.13 2363.2,1326.83 2437.16,1326.83 3144.75,619.25 3144.75,485 3175,454.75 3175,310 3195,290 4285,290 4300,305 4300,520 v1(4345,565)
USB2_HOST2_DM: J7.74 R126.1 | length 1777
  TOP w6.23: J7.74@2642.91,1953.5 2642.91,1907.91 2640,1905 2640,1590 2651.19,1578.81 2651.19,1549.88 v1(2656.07,1545) ; v1(3640.89,1000) 3632,991.12 3632,961.35 3641.23,952.12 3667.43,952.12 R126.1@3680.32,965
  BOTTOM w6.23: v1(2656.07,1545) 2820.12,1545 2914.37,1450.75 ccw(c2918.09,1454.47) 2921.81,1450.75 cw(c2925.53,1447.04) 2929.24,1450.75 2939.43,1440.57 cw(c2935.71,1436.85) 2939.43,1433.13 ccw(c2943.15,1429.41) 2939.43,1425.7 3255.12,1110 3555.12,1110 3561.18,1103.94 ccw(c3564.9,1107.66) 3568.62,1103.94 cw(c3572.34,1100.22) 3576.06,1103.94 3586.24,1093.75 cw(c3582.53,1090.04) 3586.24,1086.32 ccw(c3589.96,1082.6) 3586.24,1078.88 3596.43,1068.7 ccw(c3600.15,1072.41) 3603.87,1068.7 cw(c3607.58,1064.98) 3611.3,1068.7 3621.49,1058.51 cw(c3617.77,1054.79) 3621.49,1051.07 ccw(c3625.2,1047.36) 3621.49,1043.64 3634.17,1030.95 3634.17,1006.71 v1(3640.89,1000)
USB2_HOST2_DP: J7.72 R125.1 | length 1775
  TOP w6.23: J7.72@2623.23,1953.5 2623.23,1906.77 2625.77,1904.23 2625.77,1584.11 2636.96,1572.92 2636.96,1551.89 v1(2630.07,1545) ; v1(3614.89,1000) 3617.77,997.12 3617.77,955.45 3635.34,937.88 3667.43,937.88 R125.1@3680.32,925
  BOTTOM w6.23: v1(2630.07,1545) 2636.96,1538.12 2636.96,1537.08 2648.15,1525.88 2663.99,1525.88 2668.88,1530.77 2814.23,1530.77 3249.23,1095.77 3549.23,1095.77 3619.94,1025.06 3619.94,1005.06 v1(3614.89,1000)
USB2_HOST3_DM: J7.68 R142.2 | length 1803.4
  TOP w6.23: J7.68@2583.86,1953.5 2583.86,1904.34 2581.13,1901.61 2581.13,1846.48 ccw(c2585.57,1846.48) 2585.57,1842.05 cw(c2585.57,1837.61) 2590,1837.61 2590,1821.56 cw(c2585.57,1821.56) 2585.57,1817.13 ccw(c2585.57,1812.69) 2581.13,1812.69 2581.13,1796.64 ccw(c2585.57,1796.64) 2585.57,1792.21 cw(c2585.57,1787.77) 2590,1787.77 2590,1771.72 cw(c2585.57,1771.72) 2585.57,1767.29 ccw(c2585.57,1762.85) 2581.13,1762.85 2581.13,1533.87 2595,1520 2720,1520 2770,1570 3540,1570 3559.23,1589.23 3802.31,1589.23 ccw(c3802.31,1594.62) 3807.69,1594.62 cw(c3813.08,1594.62) 3813.08,1600 3827.23,1600 cw(c3827.23,1594.62) 3832.61,1594.62 ccw(c3838,1594.62) 3838,1589.23 3874.55,1589.23 R142.2@3890.32,1605
USB2_HOST3_DP: J7.66 R141.2 | length 1792.1
  TOP w6.23: J7.66@2564.17,1953.5 2564.17,1904.34 2566.9,1901.61 2566.9,1527.97 2589.11,1505.77 2725.89,1505.77 2775.89,1555.77 3545.89,1555.77 3565.12,1575 3880.32,1575 R141.2@3890.32,1565
USB3_HOST1_DM: J4.80 R136.2 | length 3512.2
  TOP w6.23: J4.80@1717.71,654.29 1717.71,703.45 1714.98,706.18 1714.98,769.86 1915.12,970 2785,970 3095.77,1280.77 3624.1,1280.77 3639.87,1265 3680,1265 3695,1280 3695,1301.88 v1(3700.11,1307)
  BOTTOM w6.23: v1(3700.11,1307) 3695,1312.12 3695,1459.88 3854.23,1619.11 3854.23,2155.77 3735,2275 3735,2330.32 R136.2@3750,2345.32
USB3_HOST1_DP: J4.78 R137.2 | length 3511.7
  TOP w6.23: J4.78@1698.02,654.29 1698.02,703.45 1700.75,706.18 1700.75,775.75 1909.23,984.23 2779.11,984.23 3089.88,1295 3630,1295 3645.77,1279.23 3674.11,1279.23 3680.77,1285.89 3680.77,1300.35 v1(3674.11,1307)
  BOTTOM w6.23: v1(3674.11,1307) 3680.77,1313.65 3680.77,1465.77 3840,1625 3840,2149.88 3720.77,2269.11 3720.77,2334.55 R137.2@3710,2345.32
USB3_HOST1_SSRXN: J4.60 J18.5 U18.2 U18.9 | length 4229.5
  TOP w6.23: J4.60@1520.86,654.29 1520.86,703.45 1518.13,706.18 1518.13,777.15 cw(c1524.07,777.15) 1524.07,783.08 ccw(c1524.07,789.02) 1530,789.02 1530,802.07 ccw(c1524.07,802.07) 1524.07,808 cw(c1524.07,813.94) 1518.13,813.94 1518.13,826.99 cw(c1524.07,826.99) 1524.07,832.92 ccw(c1524.07,838.86) 1530,838.86 1530,851.91 ccw(c1524.07,851.91) 1524.07,857.84 cw(c1524.07,863.78) 1518.13,863.78 1518.13,875.01 1698.13,1055 2740,1055 3075.77,1390.77 3558.77,1390.77 3565,1384.54 3565,1375.12 v1(3559.89,1370)
  BOTTOM w6.23: J18.5@3528.8,2790.12 3554.83,2790.12 3561.06,2783.89 3561.06,2754.14 3579.26,2735.94 3579.26,2710.44 3561.06,2692.24 3561.06,2629.11 3579.39,2610.77 3609.11,2610.77 3660.14,2559.74 3660.14,2512.02 3654.69,2506.57 U18.9@3654.69,2495.75 U18.2@3654.69,2464.25 3654.69,2443.63 3657.41,2440.91 3657.41,2252.46 3702.22,2207.66 cw(c3697.25,2202.69) 3702.22,2197.72 ccw(c3707.18,2192.75) 3702.21,2187.78 3709.9,2180.1 ccw(c3714.87,2185.07) 3719.84,2180.1 cw(c3724.81,2175.13) 3729.77,2180.1 3775,2134.87 3775,1934.88 3800.77,1909.11 3800.77,1655.89 3566.77,1421.89 3566.77,1376.88 v1(3559.89,1370)
USB3_HOST1_SSRXP: J4.58 J18.6 U18.1 U18.10 | length 4229.4
  TOP w6.23: J4.58@1501.17,654.29 1501.17,703.45 1503.9,706.18 1503.9,880.9 1692.23,1069.23 2734.11,1069.23 3069.88,1405 3565.43,1405 3580,1390.43 3580,1375.88 v1(3585.89,1370)
  BOTTOM w6.23: v1(3585.89,1370) 3581,1374.88 3581,1416 3815,1650 3815,1915 3789.23,1940.77 3789.23,2140.77 3671.64,2258.35 3671.64,2440.91 3674.37,2443.63 U18.1@3674.37,2464.25 U18.10@3674.37,2495.75 3674.37,2565.63 3615,2625 3585.29,2625 3575.29,2635 3575.29,2686.34 3593.49,2704.55 3593.49,2741.83 3575.29,2760.04 3575.29,2780.28 3585.12,2790.12 J18.6@3607.54,2790.12
USB3_HOST1_SSTXN: C112.2 J4.64 | length 3757.3
  TOP w6.23: J4.64@1560.23,654.29 1560.23,703.45 1557.5,706.18 1557.5,749.38 1578.4,770.27 cw(c1582.62,766.05) 1586.83,770.27 ccw(c1591.05,774.49) 1595.27,770.27 1604.46,779.46 ccw(c1600.24,783.67) 1604.46,787.89 cw(c1608.67,792.11) 1604.46,796.33 1613.64,805.51 cw(c1617.86,801.3) 1622.08,805.51 ccw(c1626.3,809.73) 1630.51,805.51 1639.7,814.7 ccw(c1635.48,818.92) 1639.7,823.14 cw(c1643.92,827.36) 1639.7,831.57 1648.88,840.76 cw(c1653.1,836.54) 1657.32,840.76 ccw(c1661.54,844.98) 1665.76,840.76 1674.94,849.94 ccw(c1670.73,854.16) 1674.94,858.38 cw(c1679.16,862.6) 1674.94,866.82 1682.89,874.76 cw(c1687.11,870.54) 1691.32,874.76 ccw(c1695.54,878.98) 1699.76,874.76 1708.95,883.95 ccw(c1704.73,888.16) 1708.95,892.38 cw(c1713.16,896.6) 1708.95,900.82 1823.9,1015.77 2765.77,1015.77 3083.73,1333.73 3771.15,1333.73 3785,1319.88 3785,1310.46 v1(3781.54,1307)
  BOTTOM w6.23: v1(3781.54,1307) 3785.77,1311.23 3785.77,1505.77 3880.77,1600.77 3880.77,2202.07 3800.77,2282.07 3800.77,2334.55 C112.2@3790,2345.32
USB3_HOST1_SSTXP: C113.2 J4.62 | length 3755.1
  TOP w6.23: J4.62@1540.54,654.29 1540.54,703.45 1543.27,706.18 1543.27,755.27 1818,1030 2759.88,1030 3077.83,1347.96 3777.05,1347.96 3800,1325 3800,1314.54 v1(3807.54,1307)
  BOTTOM w6.23: v1(3807.54,1307) 3800,1314.54 3800,1499.88 3895,1594.88 3895,2207.97 3815,2287.97 3815,2330.32 C113.2@3830,2345.32
USB20_HOST_PWR_EN: J7.67 R140.1 | length 3236.2
  TOP w6.16: J7.67@2583.86,2110.98 2583.86,2050.98 2602.31,2032.53 2737.53,2032.53 2785,2080 2785,2215 2835,2265 2835,2290 v1(2605,2520)
  ART03 w5.61: v1(2605,2520) 2605,3090 2650,3135 3435,3135 3465,3105 3465,3060 3520,3005 4219.68,3005 v1(4275,3060.32)
  BOTTOM w6.16: v1(4275,3060.32) R140.1@4305,3060.32
USB20_OTG_PWR_EN: J4.37 R149.1 | length 2549.7
  TOP w6.16: J4.37@1304.32,496.81 v1(1304.32,555)
  ART03 w5.61: v1(635,1525) 635,1280 685,1230 685,1065 824,926 1159,926 1305,780 1305,625 1325,605 1325,575.68 v1(1304.32,555)
  BOTTOM w6.16: v1(635,1525) 900,1525 930,1555 930,1940 945,1955 945,2210 974.68,2239.68 R149.1@974.68,2260
USB30_HOST_PWR_EN: J5.14 R146.1 | length 3956.9
  TOP w6.16: v1(925,2015) 945,2035 1030,2035 1068.1,1996.9 J5.14@1068.1,1953.5
  ART03 w5.61: v1(925,2015) 950,2040 950,2265 1035,2350 1365,2350 1405,2390 1405,2545 1446.81,2586.8 2241.2,2586.8 2255,2600.61 2255,3160 2270,3175 3475,3175 3525,3125 v1(3525,3060.56)
  BOTTOM w6.16: v1(3525,3060.56) R146.1@3555.39,3060.56
"USB OTG": C123.1 C124.1 J19.A4 J19.A9 J19.B4 J19.B9 R148.1 U24.1 | length 411.1
  BOTTOM w20: R148.1@945,2795.32 945,2785 v1(982,2748) v1(1014.68,2715.32) 1014.68,2690.32 1009.68,2685.32 C124.1@1009.68,2515 C123.1@1009.68,2475 1009.68,2456.93 U24.1@1039.21,2427.4
USB_OTG0_DM: J6.6 R133.2 | length 3305.8
  TOP w6.23: v1(1830,675) 1830,715 1869.76,754.76 1950.24,754.76 1970.89,734.11 1970.89,706.18 1973.62,703.45 J6.6@1973.62,654.29
  ART03 w5.66: v1(1047,2748.38) 1047,2596.32 826.34,2375.66 826.34,1494.34 1003.85,1316.83 1658.85,1316.83 1715,1260.68 1715,820.68 1757.52,778.16 ccw(c1772.17,792.82) 1757.64,778.04 1830,705.68 v1(1830,675)
  BOTTOM w6.23: R133.2@1040,2795.32 1052.88,2782.43 1052.88,2772.38 1047,2766.49 v1(1047,2748.38)
USB_OTG0_DP: J6.4 R134.2 | length 3378.2
  TOP w6.23: v1(1860,675) 1844.23,690.77 1844.23,709.1 1875.66,740.53 1889.47,740.53 1900,730 1920,730 1930.53,740.53 1944.34,740.53 1956.66,728.21 1956.66,706.18 1953.94,703.45 J6.4@1953.94,654.29
  ART03 w5.66: v1(1073,2748.38) 1065.83,2741.21 1065.83,2740.58 1060.66,2735.41 1060.66,2715.75 ccw(c1065.33,2715.75) 1065.33,2711.08 cw(c1065.33,2706.41) 1070,2706.41 1070,2693.11 cw(c1065.33,2693.11) 1065.33,2688.44 ccw(c1065.33,2683.77) 1060.66,2683.77 1060.66,2670.47 ccw(c1065.33,2670.47) 1065.33,2665.8 cw(c1065.33,2661.13) 1070,2661.13 1070,2647.83 cw(c1065.33,2647.83) 1065.33,2643.16 ccw(c1065.33,2638.49) 1060.66,2638.49 1060.66,2590.66 840,2370 840,1500 1009.51,1330.49 1664.51,1330.49 1728.66,1266.34 1728.66,977.26 ccw(c1734.33,977.26) 1734.33,971.59 cw(c1734.33,965.92) 1740,965.92 1740,954.62 cw(c1734.33,954.62) 1734.33,948.95 ccw(c1734.33,943.28) 1728.66,943.28 1728.66,931.98 ccw(c1734.33,931.98) 1734.33,926.31 cw(c1734.33,920.64) 1740,920.64 1740,909.34 cw(c1734.33,909.34) 1734.33,903.67 ccw(c1734.33,898) 1728.66,898 1728.66,886.7 ccw(c1734.33,886.7) 1734.33,881.03 cw(c1734.33,875.36) 1740,875.36 1740,864.06 cw(c1734.33,864.06) 1734.33,858.39 ccw(c1734.33,852.72) 1728.66,852.72 1728.66,826.34 1767.17,787.82 ccw(c1772.18,792.82) 1777.17,787.82 ; 1777.18,787.82 cw(c1782.17,782.82) 1787.17,787.82 ; 1787.17,787.82 1793.18,781.81 cw(c1788.18,776.81) 1793.18,771.81 ccw(c1798.18,766.82) 1793.18,761.82 1799.19,755.81 ccw(c1804.19,760.81) 1809.19,755.81 cw(c1814.19,750.8) 1819.19,755.8 1825.2,749.8 cw(c1820.2,744.8) 1825.2,739.8 ccw(c1830.2,734.8) 1825.2,729.8 1843.66,711.34 1843.66,691.34 v1(1860,675)
  BOTTOM w6.23: v1(1073,2748.38) 1073,2766.49 1067.12,2772.38 1067.12,2782.43 R134.2@1080,2795.32
USB_OTG0_ID: J6.10 R135.2 | length 3478.9
  TOP w6.16: v1(1895,620) 1915,600 2006.83,600 2012.99,606.16 J6.10@2012.99,654.29
  ART03 w5.61: v1(1300,2750) 1165,2750 1115,2700 1115,2555 865,2305 865,1510 1023.2,1351.81 1713.2,1351.81 1770,1295 1770,855 1915,710 1915,640 v1(1895,620)
  BOTTOM w6.16: v1(1300,2750) R135.2@1300,2815.32
USB_OTG0_VBUSDET: J6.12 R148.2 R150.1 | length 4031.3
  TOP w6.16: v1(1795,620) 1795,715 1875,795 1980,795 2032.68,742.32 J6.12@2032.68,654.29
  ART03 w5.61: v1(875,2834.68) 775,2734.68 775,2605 750,2580 585,2580 515,2510 515,1780 695,1600 695,1275 730,1240 730,1075 820,985 1440,985 1465,960 1465,725 1540,650 1765,650 v1(1795,620)
  BOTTOM w6.16: v1(875,2834.68) R150.1@905,2834.68 R148.2@945,2834.68
USER_LED: J5.6 R45.2 | length 5416.9
  TOP w6.16: v1(949.99,1859.13) 989.36,1898.5 J5.6@989.36,1953.5 ; v1(4410,1210) 4385,1185 4385,1160 4418,1127 4616,1127 4635,1108 4635,565 4705,495 4915,495 4975.32,434.68 R45.2@5040,434.68
  ART03 w5.61: v1(949.99,1859.13) 930,1839.14 930,1520 1050,1400 1998.77,1400 2208.77,1190 4390,1190 v1(4410,1210)
VCC3V3_SD: C51.1 C71.1 C72.1 J4.15 J4.17 J12.4 | length 655.3
  TOP w10: v1(1080.89,433.62) 1087.79,440.52 J4.15@1087.79,496.81 ; J4.17@1107.47,496.81 1107.47,442.04 v1(1115.89,433.62)
  BOTTOM w15: v1(4470,630) 4470,713.24 4502.06,745.3 4553.31,745.3 4579.68,771.67 C71.1@4579.68,775 4607.18,747.5 4660.51,747.5 4684.68,771.67 C72.1@4684.68,775 4690,775 4773.66,691.34 J12.4@4822.41,691.34
VCC3V3_SYS: C8.1 C15.1 C16.1 C17.1 L1.2 R4.1 U1.5 U6.5 U30.5 U31.5 U34.5 | length 1827.1
  TOP w15: U30.5@4887.4,2150.79 4887.4,2117.6 v1(4895,2110)
  TOP w20: v1(405,855.79) 654.79,855.79 700,901 700,1355 v1(736,1391) ; v1(4860.6,1338.15) 4885.04,1338.15 U31.5@4887.4,1335.79
  POW04 w10: v1(890,1330) v1@890,1331
  BOTTOM w10: C8.1@90.32,2015 R4.1@90.32,2055 96,2060.68 96,2291 129,2324 381,2324 395,2310 C16.1@395,2251.5
  BOTTOM w20: U6.5@367.6,855.79 v1(405,855.79) ; U1.5@857.4,1319.21 870.19,1332 888,1332 v1(890,1330) ; U34.5@4510.79,1142.4 4529.4,1142.4 4559,1172 4659,1172 v1(4690,1203)
  other v1: 535,2230 575,2230 535,2270 575,2270
VCC5V0_SYS: C20.1 C24.1 C25.1 C26.1 C47.1 C48.1 J4.1 J4.2 J4.3 J4.4 J4.5 J4.6 L2.2 R11.1 R16.1 U2.5 U28.5 U29.5 U32.5 U33.5 | length 1220.6
  TOP w10: R16.1@287,1789.68 287,1842 300,1855 430,1855 v1(455,1880)
  TOP w15: v1(4887.4,1117) U29.5@4887.4,1155.79 ; v1(4887.4,1925) U28.5@4887.4,1970.79
  BOTTOM w10: C20.1@90.32,1565 R11.1@90.32,1605 90.32,1615.32 125,1650 125,1840 140,1855 320,1855 366,1901 434,1901 v1(455,1880)
  BOTTOM w15: v1(4805,1750) 4805,1713.19 U33.5@4805.79,1712.4
  BOTTOM w20: C26.1@505,1769.68 505,1774.68 522.72,1792.4 U2.5@575.79,1792.4 ; U32.5@4780.79,2242.4 4780.79,2295.79 4800,2315 v1(4845,2315)
  other v1: 950,555 985,555 950,595 985,595 455,1840 495,1840 495,1880
VCC5V0_SYS_2: C29.1 C34.1 C35.1 C36.1 L3.2 R10.1 R20.1 U7.5 U21.5 U23.5 U24.5 | length 3001.1
  TOP w15: v1(890,2300) R10.1@923.5,2300
  ART03 w30: v1(335,1035.79) 335,1520 190,1665 190,2475 230,2515 435,2515 526,2606 526,2682.01 553.99,2710 v1(555,2710)
  BOTTOM w10: C29.1@85.32,2485 R20.1@85.32,2525 85.32,2587.78 130.03,2632.49 130.03,2780 140.03,2790 540,2790 555,2775 v1(555,2750)
  BOTTOM w15: v1(335,1035.79) U7.5@367.6,1035.79
  BOTTOM w25: v1(890,2300) 890,2455
  other v1: 595,2710 595,2750 2182.09,3158.34 2222.09,3158.34
VCC5V0_USB20_HOST: C110.1 C111.1 C114.1 C115.1 J20.1 J20.7 U21.1 | length 265.9
  BOTTOM w30: C111.1@4529.68,2905 4572.9,2861.78 J20.7@4572.9,2775.15 J20.1@4572.9,2657.04
VCC5V0_USB30_HOST: C120.1 C121.1 J18.1 J18.10 U23.1 | length 142.3
  TOP w20: J18.10@3824.08,2723.19 3804.39,2742.88 3804.39,2829.48 J18.1@3824.08,2849.17
VCC_1V8: C49.1 C54.1 C55.1 C103.1 J4.11 J4.13 L7.2 R36.1 R37.1 U8.8 | length 1141.9
  TOP w10: v1(1040,555) 1048.42,546.58 J4.11@1048.42,496.81 ; J4.13@1068.1,496.81 1068.1,548.1 v1(1075,555)
  TOP w15: U8.8@3345,602.52 3345,665 3370.32,690.32 C55.1@3405,690.32 C54.1@3445,690.32 v1(3475,690.32) 3475,765 3454.68,785.32 R36.1@3445,785.32 R37.1@3405,785.32 ; L7.2@3655,1706.5 3666.82,1694.68 C103.1@3705,1694.68 v1(3731.8,1694.68)
  BOTTOM w20: v1(3475,1253) 3475,1437.88 v1(3731.8,1694.68) 3732.12,1695 v1(3765,1695)
VCC_12V: C1.1 C2.1 C3.1 C12.1 C13.1 C14.1 C21.1 C22.1 C23.1 C31.1 C32.1 C33.1 C38.1 C151.1 C156.1 C157.1 C158.1 D1.1 F1.2 R7.1 R9.1 R14.1 R23.1 R26.1 R27.1 R193.1 R195.1 U3.3 U4.3 U5.3 U35.3 | length 840.4
  TOP w20: 425,2110 585,2110 655,2180 863.5,2180 R9.1@923.5,2240
  BOTTOM w10: R7.1@280,1895.32 310.32,1895.32 345,1930 345,1973.52 ; R14.1@300,1425.32 332.18,1425.32 334.86,1428 350,1428 ; R23.1@300,2365.32 309.68,2375 v1(410,2375)
  other v1: 4735,965 4770,965 510,1345 550,1345 495,1485 535,1485 575,1485 495,1525 535,1525 575,1525 4530,1640 4570,1640 4610,1640 495,1955 535,1955 495,1995 535,1995 450,2375 410,2415 450,2415
VCC_RTC: J4.18 R51.2 | length 2153.3
  TOP w10: v1(1005,1245) 1085,1245 1107.47,1222.53 J4.18@1107.47,654.29
  TOP w15: v1(719.68,2230) 750,2260.32 750,2325 780,2355 780,2449.68 R51.2@749.68,2480
  ART03 w15: v1(719.68,2230) 620,2130.32 620,1785 768.5,1636.5 768.5,1481.91 1005,1245.41 v1(1005,1245)
VCCA_1V8: C50.1 J4.12 J4.14 R34.1 R227.2 | length 3460.5
  TOP w10: R227.2@224.68,1575 265,1575 350,1490 350,1220 v1(375,1195) ; v1(1040,595) 1048.42,603.42 J4.12@1048.42,654.29
  ART03 w20: v1(375,1195) 380,1190 380,975 395,960 440,960 540,860 585,860 703,742 933,742 1040,635 v1(1040,595)
  ART03 w25: v1(1040,595) 1013.5,568.5 1013.5,501.5 1045,470 1248.7,470 1448.7,270 2110,270 v1(2160,320)
  BOTTOM w10: R34.1@2070,635.32 2050,615.32 2050,540 2060,530 2140,530 2160,510 v1(2160,320)
  BOTTOM w15: v1(1040,595) C50.1@1040,680.32
VCCIO_ACODEC: C52.1 C172.1 C177.1 J4.19 J4.21 R212.1 R214.1 | length 4961.1
  TOP w10: J4.19@1127.16,496.81 1127.16,545.5 1137.16,555.5 v1(1137.5,555.5) 1146.84,546.16 J4.21@1146.84,496.81
  TOP w15: v1(1700,2925) 1700,2685 1795,2590 1795,2475 1775.32,2455.32 C177.1@1765,2455.32 R214.1@1725,2455.32 C172.1@1725,2349.68 R212.1@1765,2349.68
  ART03 w25: v1(1137.5,555.5) 1110,583 1110,745 1068.5,786.5 713.5,786.5 580,920 545,920 490,975 490,1190 385,1295 385,1554.69 240,1699.69 240,2315 285,2360 285,2445 310,2470 440,2470 841.5,2871.5 1366.5,2871.5 1420,2925 v1(1700,2925)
